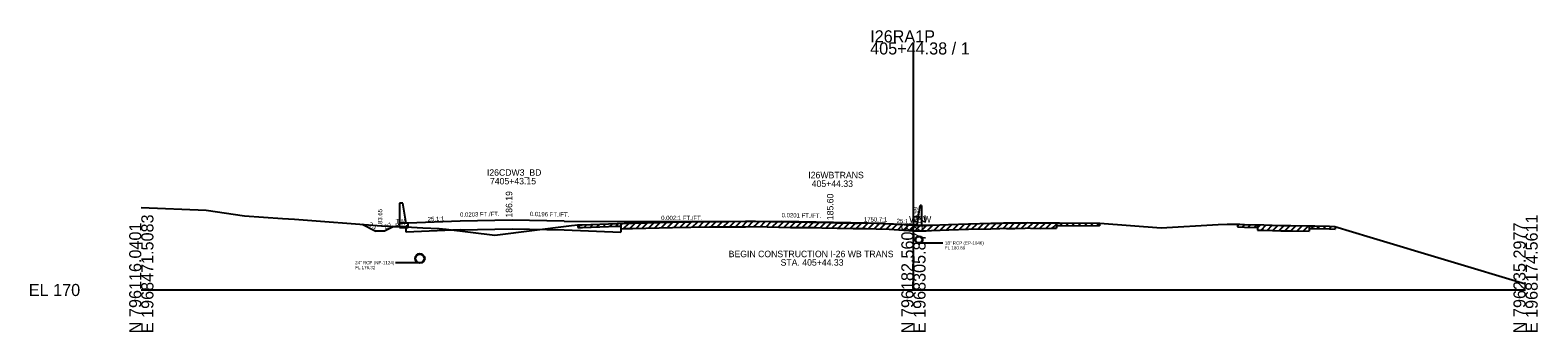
# Model space of a CAD drawing. Extents: x -44 to 4323, y -10 to 9601.
# Drawn here: x -44.2 to 304.3, y 3989.3 to 4059.1 of the extents above; entities that cross this region are included whole.
import ezdxf

# ---------------------------------------------------------------- set-up
doc = ezdxf.new("R2010")
doc.units = 0
for name, color, linetype in [('1', 7, 'Continuous'), ('DateStamp', 7, 'Continuous'), ('NotForConst', 7, 'Continuous'), ('QCQA', 7, 'Continuous'), ('RD_SHT_Bndy', 7, 'Continuous'), ('RD_SHT_Iplotshp', 7, 'Continuous'), ('RD_SHT_TX', 7, 'Continuous'), ('RD_Sketch10', 7, 'Continuous'), ('RD_XS_ExGround', 7, 'Continuous'), ('RD_XS_ExPaveRet', 7, 'Continuous'), ('RD_XS_MatchLine', 7, 'Continuous'), ('RD_XS_Misc_Line', 7, 'Continuous'), ('RD_XS_PaveShd', 7, 'Continuous'), ('RD_XS_Pipe', 7, 'Continuous'), ('RD_XS_TX_Elev_PR', 7, 'Continuous'), ('RD_XS_TX_Profile', 7, 'Continuous'), ('RD_XS_TX_ShdSlope', 7, 'Continuous'), ('RD_XS_TX_Slope', 7, 'Continuous'), ('seal', 7, 'Continuous'), ('TR SN EXTRUDED PANEL SIGNS - GROUND MOUNTED', 7, 'Continuous')]:
    doc.layers.add(name, color=color, linetype=linetype)

msp = doc.modelspace()

# ---------------------------------------------------------------- linework, layer by layer
at = {"layer": 'DateStamp'}
msp.add_lwpolyline([(-18.49, 4018.1), (-3.5, 4017.45), (5.39, 4016.19), (14.12, 4015.57), (16.96, 4015.43), (37.01, 4013.86), (42.69, 4013.58), (46.56, 4013.41), (50.33, 4013.26), (52.02, 4013.05), (63.21, 4011.69), (80.99, 4013.89), (82.4, 4014.07), (83.45, 4014.11), (91.51, 4014.39), (93.15, 4014.45), (95, 4014.5), (104.3, 4014.73), (112.82, 4014.83), (117.04, 4014.87), (121.18, 4014.9), (123.47, 4014.91), (126.95, 4014.84), (131.6, 4014.75), (135.87, 4014.72), (137.24, 4014.71), (138.86, 4014.66), (142.37, 4014.58), (143.2, 4014.56), (146.08, 4014.48), (147.04, 4014.49), (149.09, 4014.51), (151.39, 4014.44), (154.48, 4014.33), (157.87, 4014.12), (160.13, 4013.98), (162.2, 4013.98), (162.91, 4013.98), (164.09, 4014.03), (168.14, 4014.18), (172.7, 4014.3), (177.89, 4014.43), (179.96, 4014.5), (180.82, 4014.53), (181.52, 4014.52), (183.43, 4014.51), (185.81, 4014.58), (186.46, 4014.6), (187.06, 4014.58), (189.41, 4014.52), (191.88, 4014.57), (193.8, 4014.55), (202.63, 4014.48), (203.09, 4014.48), (217.24, 4013.38), (230.44, 4014.13), (232.55, 4014.23), (233.95, 4014.22), (234.99, 4014.21), (235.45, 4014.2), (236.53, 4014.16), (241.02, 4014.06), (244.94, 4013.96), (247.21, 4013.92), (251.57, 4013.85), (252.27, 4013.84), (252.82, 4013.84), (256.19, 4013.75), (257.42, 4013.73), (265.6, 4011.25), (301.51, 4000.39)], dxfattribs=at)
at = {"layer": 'NotForConst'}
for p, q in [((82.42, 4013.45), (83.07, 4014.1)), ((83.89, 4013.5), (84.54, 4014.15)), ((85.35, 4013.55), (86, 4014.2)), ((86.82, 4013.6), (87.47, 4014.25)), ((88.28, 4013.65), (88.93, 4014.3)), ((89.75, 4013.7), (90.4, 4014.35)), ((91.21, 4013.75), (91.86, 4014.4)), ((92.4, 4014.03), (92.81, 4014.44)), ((92.98, 4013.2), (94.27, 4014.48)), ((94.43, 4013.23), (95.72, 4014.52)), ((95.88, 4013.27), (97.17, 4014.55)), ((97.33, 4013.3), (98.62, 4014.59)), ((98.78, 4013.34), (100.07, 4014.62)), ((100.23, 4013.38), (101.52, 4014.66)), ((101.68, 4013.41), (102.97, 4014.69)), ((103.13, 4013.45), (104.41, 4014.73)), ((104.58, 4013.48), (105.85, 4014.75)), ((106.01, 4013.5), (107.28, 4014.76)), ((107.44, 4013.52), (108.71, 4014.78)), ((108.88, 4013.53), (110.14, 4014.8)), ((110.31, 4013.55), (111.57, 4014.82)), ((111.74, 4013.57), (113, 4014.83)), ((113.17, 4013.58), (114.43, 4014.85)), ((114.6, 4013.6), (115.86, 4014.86)), ((116.03, 4013.61), (117.29, 4014.88)), ((117.45, 4013.63), (118.71, 4014.88)), ((118.88, 4013.63), (120.13, 4014.89)), ((120.3, 4013.64), (121.55, 4014.9)), ((121.72, 4013.65), (122.98, 4014.9)), ((123.14, 4013.66), (124.38, 4014.89)), ((124.54, 4013.64), (125.76, 4014.86)), ((125.92, 4013.61), (127.15, 4014.84)), ((127.31, 4013.58), (128.54, 4014.81)), ((128.7, 4013.56), (129.93, 4014.79)), ((130.09, 4013.53), (131.32, 4014.76)), ((131.48, 4013.51), (132.71, 4014.74)), ((132.88, 4013.49), (134.12, 4014.73)), ((134.28, 4013.48), (135.52, 4014.72)), ((135.68, 4013.47), (136.92, 4014.71)), ((137.08, 4013.46), (138.31, 4014.68)), ((138.47, 4013.42), (139.69, 4014.64)), ((139.84, 4013.39), (141.06, 4014.61)), ((141.22, 4013.35), (142.44, 4014.57)), ((142.6, 4013.32), (143.83, 4014.54)), ((143.99, 4013.29), (145.2, 4014.51)), ((145.36, 4013.25), (146.6, 4014.49)), ((146.76, 4013.24), (148.03, 4014.5)), ((148.19, 4013.25), (149.44, 4014.5)), ((149.6, 4013.24), (150.81, 4014.46)), ((150.97, 4013.2), (152.18, 4014.41)), ((152.34, 4013.15), (153.55, 4014.36)), ((153.71, 4013.11), (154.9, 4014.31)), ((155.06, 4013.04), (156.24, 4014.22)), ((156.39, 4012.96), (157.57, 4014.14)), ((157.72, 4012.88), (158.9, 4014.06)), ((159.05, 4012.79), (160.23, 4013.98)), ((160.4, 4012.73), (161.65, 4013.98)), ((161.82, 4012.73), (163.07, 4013.99)), ((163.24, 4012.74), (164.54, 4014.05)), ((164.71, 4012.8), (166.01, 4014.1)), ((166.18, 4012.85), (167.48, 4014.15)), ((167.65, 4012.91), (168.94, 4014.2)), ((169.11, 4012.95), (170.39, 4014.24)), ((170.56, 4012.99), (171.84, 4014.27)), ((172.01, 4013.03), (173.3, 4014.31)), ((173.46, 4013.07), (174.75, 4014.35)), ((174.92, 4013.1), (176.2, 4014.39)), ((176.37, 4013.14), (177.65, 4014.43)), ((177.82, 4013.18), (179.11, 4014.47)), ((179.28, 4013.23), (180.57, 4014.52)), ((180.74, 4013.27), (181.98, 4014.52)), ((182.15, 4013.26), (183.39, 4014.51)), ((183.56, 4013.26), (184.84, 4014.55)), ((185.01, 4013.3), (186.3, 4014.59)), ((186.47, 4013.35), (187.69, 4014.56)), ((187.85, 4013.31), (189.07, 4014.53)), ((189.23, 4013.28), (190.5, 4014.54)), ((190.67, 4013.3), (191.94, 4014.57)), ((192.1, 4013.32), (193.04, 4014.26)), ((193.04, 4014.46), (193.14, 4014.56)), ((193.92, 4013.92), (194.54, 4014.54)), ((195.32, 4013.91), (195.94, 4014.53)), ((196.72, 4013.9), (197.34, 4014.52)), ((198.13, 4013.89), (198.75, 4014.51)), ((199.53, 4013.88), (200.15, 4014.5)), ((200.93, 4013.87), (201.55, 4014.49)), ((202.34, 4013.86), (202.96, 4014.48)), ((234.9, 4013.87), (235.23, 4014.2)), ((236, 4013.56), (236.6, 4014.16)), ((237.38, 4013.52), (237.99, 4014.13)), ((238.76, 4013.49), (239.37, 4014.1)), ((239.52, 4013.4), (240.2, 4014.08)), ((240.36, 4012.82), (241.58, 4014.05)), ((241.74, 4012.79), (242.96, 4014.01)), ((243.12, 4012.76), (244.34, 4013.98)), ((244.5, 4012.72), (245.73, 4013.95)), ((245.89, 4012.7), (247.12, 4013.93)), ((247.28, 4012.67), (248.51, 4013.9)), ((248.67, 4012.65), (249.9, 4013.88)), ((250.07, 4012.63), (251.3, 4013.86)), ((251.46, 4012.61), (251.52, 4012.67)), ((251.95, 4013.22), (252.57, 4013.84)), ((253.34, 4013.2), (253.95, 4013.81)), ((254.72, 4013.16), (255.33, 4013.78)), ((256.1, 4013.13), (256.71, 4013.74)), ((257.48, 4013.1), (257.52, 4013.14))]:
    msp.add_line(p, q, dxfattribs=at)
at = {"layer": 'QCQA'}
msp.add_line((92.4, 4014.42), (92.4, 4012.39), dxfattribs=at)
at = {"layer": 'RD_SHT_Bndy'}
for p, q in [((160, 3999), (160, 4056.3)), ((-18.49, 3999), (160, 3999)), ((160, 3999), (301.51, 3999))]:
    msp.add_line(p, q, dxfattribs=at)
at = {"layer": 'RD_SHT_Iplotshp'}
for p, q in [((82.4, 4014.07), (82.4, 4013.45)), ((92.4, 4014.42), (92.4, 4013.17)), ((193.04, 4014.56), (193.04, 4013.31)), ((203.04, 4014.48), (203.04, 4013.85)), ((234.9, 4014.21), (234.9, 4013.59)), ((239.52, 4014.09), (239.52, 4012.84)), ((251.52, 4013.85), (251.52, 4012.6)), ((257.52, 4013.69), (257.52, 4013.1))]:
    msp.add_line(p, q, dxfattribs=at)
for points in [[(82.4, 4013.45), (83.47, 4013.48), (91.53, 4013.76), (92.4, 4013.8)], [(92.4, 4013.17), (93.18, 4013.2), (95.03, 4013.25), (104.33, 4013.48), (112.84, 4013.58), (117.05, 4013.62), (121.19, 4013.65), (123.46, 4013.66), (131.58, 4013.5), (135.86, 4013.47), (137.22, 4013.46), (138.83, 4013.41), (142.34, 4013.33), (143.17, 4013.31), (146.07, 4013.23), (147.05, 4013.24), (149.08, 4013.26), (151.35, 4013.19), (154.42, 4013.08), (157.79, 4012.87), (160.09, 4012.73), (162.2, 4012.73), (162.93, 4012.73), (164.14, 4012.78), (168.18, 4012.93), (172.73, 4013.05), (177.92, 4013.18), (180, 4013.25), (180.83, 4013.28), (181.51, 4013.27), (183.44, 4013.26), (185.85, 4013.33), (186.46, 4013.35), (187.03, 4013.33), (189.41, 4013.27), (191.88, 4013.32), (193.04, 4013.31)], [(193.04, 4013.93), (193.8, 4013.92), (203.04, 4013.85)], [(234.9, 4013.59), (236.51, 4013.54), (239.52, 4013.47)], [(239.52, 4012.84), (240.99, 4012.81), (244.91, 4012.71), (247.19, 4012.67), (251.52, 4012.6)], [(251.52, 4013.23), (251.56, 4013.23), (252.26, 4013.22), (252.8, 4013.21), (256.18, 4013.13), (257.52, 4013.1)]]:
    msp.add_lwpolyline(points, dxfattribs=at)
at = {"layer": 'RD_XS_ExPaveRet'}
for p, q in [((41.2, 4016.38), (41.2, 4014.46)), ((41.2, 4014.46), (41.2, 4015.38)), ((43.21, 4014.46), (41.2, 4014.46))]:
    msp.add_line(p, q, dxfattribs=at)
at = {"layer": 'RD_XS_Misc_Line'}
for p, q in [((42.7, 4013.88), (43.21, 4013.9)), ((42.7, 4012.4), (42.7, 4013.88)), ((55.23, 4012.9), (42.7, 4012.4)), ((43.21, 4013.9), (43.21, 4014.46)), ((55.23, 4012.9), (67.26, 4013.15)), ((67.26, 4013.15), (79.28, 4012.91)), ((79.28, 4012.91), (92.4, 4012.39))]:
    msp.add_line(p, q, dxfattribs=at)
at = {"layer": 'RD_XS_PaveShd'}
for p, q in [((32.6, 4014.21), (35.71, 4012.65)), ((37.71, 4012.65), (35.71, 4012.65)), ((39.71, 4013.65), (37.71, 4012.65)), ((41.21, 4013.65), (39.71, 4013.65))]:
    msp.add_line(p, q, dxfattribs=at)
at = {"layer": 'RD_XS_Pipe'}
for p, q in [((161.78, 4009.88), (166.78, 4009.88)), ((45.25, 4005.32), (40.25, 4005.32))]:
    msp.add_line(p, q, dxfattribs=at)
for centre, radius in [((161.28, 4010.63), 0.85), ((161.28, 4010.63), 0.75), ((45.92, 4006.32), 1.1), ((45.92, 4006.32), 1)]:
    msp.add_circle(centre, radius, dxfattribs=at)
at = {"layer": 'RD_XS_TX_Elev_PR'}
for p, q in [((161.86, 4018.54), (161.86, 4018.54)), ((55.23, 4014.94), (43.21, 4014.46)), ((79.28, 4014.95), (129.51, 4014.84)), ((153.51, 4014.36), (160.86, 4014.06)), ((160.86, 4014.06), (160.86, 4013.98))]:
    msp.add_line(p, q, dxfattribs=at)
at = {"layer": 'RD_XS_TX_ShdSlope'}
for p, q in [((41.96, 4019.13), (41.21, 4019.13)), ((41.21, 4019.13), (41.21, 4013.46)), ((42.71, 4014.46), (41.96, 4019.13)), ((160.86, 4014.06), (161.53, 4018.54)), ((161.86, 4018.54), (161.53, 4018.54)), ((161.86, 4018.54), (161.86, 4013.98)), ((41.21, 4013.46), (43.21, 4013.46)), ((43.21, 4014.46), (42.71, 4014.46)), ((43.21, 4013.46), (43.21, 4014.46))]:
    msp.add_line(p, q, dxfattribs=at)
at = {"layer": 'RD_XS_TX_Slope'}
for p, q in [((67.26, 4015.19), (55.23, 4014.94)), ((79.28, 4014.95), (67.26, 4015.19)), ((141.51, 4014.6), (129.51, 4014.84)), ((153.51, 4014.36), (141.51, 4014.6))]:
    msp.add_line(p, q, dxfattribs=at)

# ---------------------------------------------------------------- texts
at = {"layer": '1'}
for s, p in [('I26CDW3_BD', (61.4, 4025.44)), ('I26WBTRANS', (135.7, 4024.85)), ('7405+43.15', (62.11, 4023.44)), ('405+44.33', (136.49, 4022.85))]:
    msp.add_text(s, height=1.5, dxfattribs=at).set_placement(p)
at = {"layer": 'RD_SHT_Bndy'}
for s, p in [('I26RA1P', (150, 4056.3)), ('405+44.38 / 1', (150, 4053.5)), ('EL 170', (-44.49, 3997.6))]:
    msp.add_text(s, height=2.8, dxfattribs=at).set_placement(p)
for s, p in [('E 1968471.5083', (-15.69, 3989)), ('E 1968305.8742', (162.8, 3989)), ('E 1968174.5611', (304.31, 3989)), ('N 796116.0401', (-18.49, 3989)), ('N 796182.5608', (160, 3989)), ('N 796235.2977', (301.51, 3989))]:
    msp.add_text(s, height=2.8, rotation=90, dxfattribs=at).set_placement(p)
at = {"layer": 'RD_SHT_TX'}
msp.add_text('184.99', height=1, rotation=90, dxfattribs=at).set_placement((161, 4013.99))
at = {"layer": 'RD_Sketch10'}
for s, p in [('TW', (40.29, 4014.46)), ('BW', (40.23, 4013.46))]:
    msp.add_text(s, height=1, dxfattribs=at).set_placement(p)
at = {"layer": 'RD_XS_ExGround'}
for s, rotation, p in [('25.1:1', 2.2857, (47.73, 4014.89)), ('1750.7:1', 359.9673, (148.57, 4014.84)), ('25:1', 357.7096, (156.11, 4014.5))]:
    msp.add_text(s, height=1, rotation=rotation, dxfattribs=at).set_placement(p)
at = {"layer": 'RD_XS_MatchLine'}
for s, p in [('BEGIN CONSTRUCTION I-26 WB TRANS', (117.29, 4006.59)), ('STA. 405+44.33', (129.29, 4004.63))]:
    msp.add_text(s, height=1.5, dxfattribs=at).set_placement(p)
at = {"layer": 'RD_XS_Pipe'}
for s, p in [('18" RCP (EP-1046)', (167.28, 4009.5)), ('FL 180.88', (167.28, 4008.38)), ('24" RCP (NP-1124)', (30.94, 4004.94)), ('FL 176.32', (30.94, 4003.82))]:
    msp.add_text(s, height=0.75, dxfattribs=at).set_placement(p)
at = {"layer": 'RD_XS_TX_Profile'}
msp.add_text('WBW', height=1.5, dxfattribs=at).set_placement((159, 4014.61))
at = {"layer": 'seal'}
for s, p in [(' 186.19', (67.26, 4015.19)), (' 185.60', (141.51, 4014.6))]:
    msp.add_text(s, height=1.5, rotation=90, dxfattribs=at).set_placement(p)
at = {"layer": 'TR SN EXTRUDED PANEL SIGNS - GROUND MOUNTED'}
for s, rotation, p in [('183.65', 90, (37.21, 4013.51)), ('0.0203 FT./FT.', 1.1602, (55.21, 4015.94)), ('0.0196 FT./FT.', 358.8785, (71.3, 4016.11)), ('0.002:1 FT./FT.', 359.8739, (101.69, 4015.19)), ('0.0201 FT./FT.', 358.8496, (129.53, 4015.84)), ('2:1', 333.4349, (34.02, 4013.87)), ('2:1', 26.5651, (37.9, 4013.04))]:
    msp.add_text(s, height=1, rotation=rotation, dxfattribs=at).set_placement(p)

doc.saveas('drawing.dxf')
